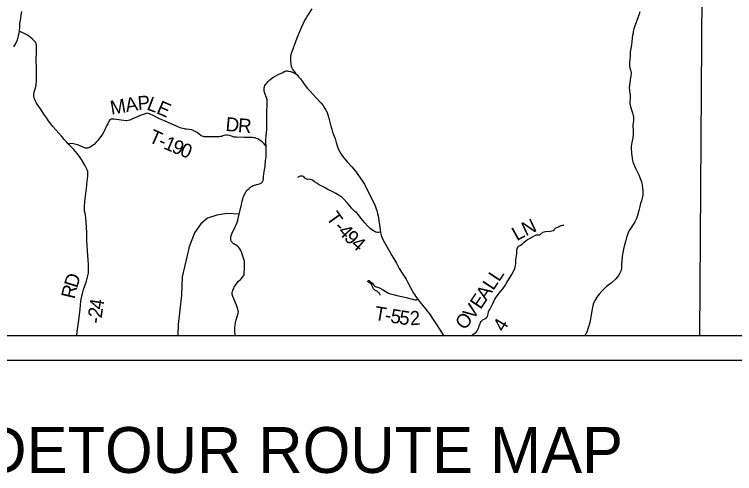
# Model space of a CAD drawing. Extents: x 0 to 191, y 0 to 55.
# Drawn here: x 22.6 to 26.995, y 8.927 to 11.729 of the extents above; entities that cross this region are included whole.
import ezdxf

# ---------------------------------------------------------------- set-up
doc = ezdxf.new("R2010")
doc.units = 0
for name, color, linetype in [('GM_X_County_Road', 7, 'Continuous'), ('GM_X_County_Road_Text', 7, 'Continuous'), ('GM_X_State_Route', 7, 'Continuous'), ('GM_X_Township_Road', 7, 'Continuous'), ('GM_X_Township_Road_Text', 7, 'Continuous'), ('GM_X_Township_Text', 7, 'Continuous'), ('SH_Data', 7, 'Continuous'), ('SH_Text', 7, 'Continuous')]:
    doc.layers.add(name, color=color, linetype=linetype)

msp = doc.modelspace()

# ---------------------------------------------------------------- linework, layer by layer
at = {"layer": 'GM_X_County_Road'}
for points in [[(24.4155, 11.7632), (24.389, 11.7228), (24.3798, 11.7084), (24.3732, 11.6965), (24.362, 11.6737), (24.3503, 11.6469), (24.3407, 11.6225), (24.3237, 11.5829), (24.3148, 11.5604), (24.2923, 11.5008), (24.289, 11.4913), (24.2866, 11.4819), (24.285, 11.4719), (24.2842, 11.4593), (24.2841, 11.4441), (24.2863, 11.427), (24.2895, 11.4129), (24.2938, 11.4026), (24.2999, 11.39), (24.3086, 11.3779), (24.3184, 11.366)], [(22.9807, 9.7697), (22.9831, 9.7942), (22.9867, 9.8209), (22.9935, 9.8627), (23.0015, 9.9305), (23.0062, 9.9785), (23.0092, 9.9993), (23.0148, 10.0251), (23.0225, 10.0508), (23.0397, 10.1012), (23.0483, 10.1332), (23.0519, 10.1522), (23.0527, 10.1756), (23.0522, 10.2014), (23.0504, 10.2331), (23.0477, 10.2553), (23.0421, 10.3484), (23.0409, 10.3987), (23.0365, 10.4894), (23.0346, 10.5022), (23.0314, 10.5161), (23.0286, 10.5278), (23.027, 10.5389), (23.0267, 10.5467), (23.0271, 10.5568), (23.0298, 10.5826), (23.0322, 10.6042), (23.037, 10.6522), (23.0409, 10.6857), (23.0418, 10.6928), (23.0443, 10.7095), (23.0476, 10.7425), (23.0484, 10.7575), (23.0473, 10.7697), (23.0458, 10.7757), (23.0442, 10.7804), (23.0383, 10.7934), (23.0296, 10.8089), (23.0084, 10.843), (22.9963, 10.8615), (22.9826, 10.8794), (22.9626, 10.9052), (22.9427, 10.9257), (22.9283, 10.9393), (22.9171, 10.9508), (22.9041, 10.9652), (22.8886, 10.9835), (22.852, 11.0237), (22.8348, 11.0443), (22.8217, 11.0612), (22.8084, 11.079), (22.7968, 11.0947), (22.7796, 11.1206), (22.7624, 11.1469), (22.7485, 11.1673), (22.7391, 11.1803), (22.7323, 11.1919), (22.7263, 11.2033), (22.7221, 11.2139), (22.7204, 11.2225), (22.719, 11.2306), (22.7186, 11.2406), (22.721, 11.2544), (22.7244, 11.2677), (22.7277, 11.2789), (22.7317, 11.2986), (22.7345, 11.3236), (22.7351, 11.3395), (22.7351, 11.3539), (22.7349, 11.376), (22.7343, 11.4064), (22.7332, 11.4474), (22.7346, 11.5038), (22.7354, 11.5236), (22.7346, 11.541), (22.7328, 11.5508), (22.729, 11.5584), (22.7228, 11.5659), (22.7086, 11.5797), (22.6947, 11.5914), (22.6797, 11.6021), (22.6601, 11.6123), (22.6427, 11.6201), (22.6301, 11.6241)], [(24.3184, 11.366), (24.3246, 11.3591), (24.3344, 11.3482), (24.3452, 11.335), (24.3742, 11.2951), (24.3877, 11.2776), (24.4021, 11.2618), (24.4394, 11.2213), (24.4702, 11.1893), (24.4835, 11.1733), (24.4946, 11.1556), (24.4999, 11.1451), (24.5077, 11.1295), (24.513, 11.1161), (24.5198, 11.0948), (24.5253, 11.0712), (24.5309, 11.0469), (24.5365, 11.0278), (24.5421, 11.0108), (24.5566, 10.9714), (24.5634, 10.9478), (24.5693, 10.9259), (24.5759, 10.9089), (24.585, 10.8911), (24.5942, 10.8752), (24.6024, 10.8638), (24.6312, 10.8294), (24.6586, 10.798), (24.6813, 10.7721), (24.6957, 10.7524), (24.711, 10.7307), (24.7291, 10.7041), (24.7363, 10.6919), (24.7451, 10.6753), (24.7573, 10.6512), (24.7645, 10.634), (24.7928, 10.5784), (24.8013, 10.5603), (24.8056, 10.5493), (24.8119, 10.5309), (24.8165, 10.5148), (24.82, 10.5004), (24.825, 10.4707), (24.8285, 10.4454), (24.8304, 10.4267), (24.8316, 10.4171), (24.8323, 10.4108), (24.8336, 10.3994), (24.8358, 10.3885), (24.8387, 10.3789), (24.8442, 10.365), (24.8509, 10.3512), (24.8586, 10.3372), (24.8668, 10.3225), (24.8916, 10.2794), (24.9043, 10.2573), (24.9196, 10.2317), (24.9316, 10.2111), (24.9404, 10.1943), (24.9482, 10.179), (24.9559, 10.1663), (24.963, 10.1553), (24.9785, 10.1317), (24.9901, 10.1135), (25.003, 10.0896), (25.0197, 10.0592), (25.0363, 10.0274), (25.0409, 10.0193), (25.0471, 10.0097), (25.0538, 10.0005), (25.0599, 9.9924), (25.0705, 9.9788), (25.0897, 9.9549), (25.1087, 9.9319), (25.123, 9.9149), (25.1323, 9.9025), (25.156, 9.8666), (25.1757, 9.8359), (25.1936, 9.8079), (25.2186, 9.7697)]]:
    msp.add_lwpolyline(points, dxfattribs=at)
at = {"layer": 'GM_X_State_Route'}
msp.add_lwpolyline([(22.5966, 11.5314), (22.6028, 11.5405), (22.6087, 11.5515), (22.6181, 11.574), (22.625, 11.597), (22.6301, 11.6241), (22.6312, 11.6313), (22.6323, 11.6514), (22.6336, 11.6745), (22.6384, 11.7042), (22.6416, 11.7243), (22.6459, 11.746)], dxfattribs=at)
at = {"layer": 'GM_X_Township_Road'}
for points in [[(26.4166, 11.7439), (26.4105, 11.7234), (26.4057, 11.7086), (26.4014, 11.6979), (26.3942, 11.6803), (26.3866, 11.6596), (26.381, 11.6412), (26.3769, 11.6241), (26.3752, 11.6142), (26.3728, 11.6011), (26.3702, 11.5837), (26.3652, 11.5427), (26.3616, 11.52), (26.3586, 11.4974), (26.357, 11.4765), (26.3553, 11.451), (26.3545, 11.4374), (26.3541, 11.4263), (26.3542, 11.4161), (26.3563, 11.4019), (26.3613, 11.3819), (26.3634, 11.3735), (26.3638, 11.3662), (26.3626, 11.3543), (26.3605, 11.3428), (26.3578, 11.3273), (26.3553, 11.3124), (26.3533, 11.2957), (26.3523, 11.2843), (26.3521, 11.2777), (26.3529, 11.2663), (26.3538, 11.2572), (26.3563, 11.2478), (26.3576, 11.2413), (26.3583, 11.2351), (26.3586, 11.2264), (26.3585, 11.218), (26.3563, 11.1929), (26.3567, 11.1836), (26.3577, 11.1771), (26.3595, 11.1684), (26.3624, 11.1581), (26.3666, 11.1455), (26.3723, 11.1275), (26.3747, 11.1196), (26.3761, 11.1126), (26.3777, 11.1013), (26.3781, 11.0883), (26.3777, 11.0782), (26.3762, 11.0701), (26.3744, 11.0547), (26.3747, 11.0414), (26.3758, 11.0294), (26.3766, 11.0122), (26.376, 10.998), (26.3736, 10.9755), (26.3678, 10.9475), (26.3652, 10.9344), (26.3639, 10.9219), (26.3646, 10.904), (26.3661, 10.8881), (26.3668, 10.8774), (26.3677, 10.8673), (26.3698, 10.8524), (26.3721, 10.8379), (26.3746, 10.8285), (26.3782, 10.8186), (26.3841, 10.8044), (26.3926, 10.7857), (26.4105, 10.7491), (26.4234, 10.7182), (26.4269, 10.7076), (26.4286, 10.6985), (26.4304, 10.6864), (26.436, 10.6523), (26.4346, 10.6277), (26.4318, 10.6085), (26.4269, 10.5905), (26.4212, 10.5741), (26.4168, 10.5556), (26.4106, 10.5321), (26.4023, 10.5009), (26.3962, 10.4826), (26.3932, 10.4745), (26.3871, 10.4632), (26.3753, 10.4461), (26.3616, 10.4252), (26.3525, 10.4096), (26.3459, 10.3958), (26.3353, 10.3669), (26.3292, 10.3437), (26.3222, 10.314), (26.3169, 10.2967), (26.3085, 10.2527), (26.3062, 10.2194), (26.3055, 10.2094), (26.3054, 10.1886), (26.3041, 10.1758), (26.303, 10.1702), (26.3009, 10.1626), (26.2949, 10.149), (26.2871, 10.1355), (26.2713, 10.1144), (26.2422, 10.0898), (26.2138, 10.0681), (26.2041, 10.0592), (26.1972, 10.052), (26.1854, 10.0395), (26.1692, 10.0214), (26.1608, 10.011), (26.1482, 9.9933), (26.1423, 9.9838), (26.1378, 9.9752), (26.1327, 9.9617), (26.1293, 9.9499), (26.1236, 9.9193), (26.1155, 9.8722), (26.111, 9.8493), (26.1017, 9.8169), (26.0955, 9.7966), (26.091, 9.7853), (26.087, 9.7785), (26.0821, 9.7716), (26.0797, 9.7697)], [(23.9468, 9.7697), (23.9459, 9.7998), (23.9459, 9.8192), (23.9475, 9.8304), (23.9496, 9.8458), (23.9539, 9.8641), (23.9613, 9.8922), (23.9654, 9.9052), (23.9666, 9.9129), (23.9661, 9.9202), (23.9633, 9.9303), (23.9599, 9.9414), (23.9555, 9.9537), (23.9386, 9.9929), (23.9333, 10.007), (23.9312, 10.0132), (23.9294, 10.0202), (23.9298, 10.0289), (23.9314, 10.0386), (23.9337, 10.0469), (23.9384, 10.0571), (23.9421, 10.0652), (23.9492, 10.077), (23.9588, 10.0899), (23.9685, 10.1005), (23.9814, 10.1125), (23.9947, 10.1279), (23.9982, 10.1327), (24.0011, 10.1406), (24.0028, 10.1517), (24.0037, 10.1811), (24.0038, 10.2086), (24.0032, 10.2222), (24.0005, 10.2351), (23.9966, 10.2483), (23.9908, 10.2652), (23.9867, 10.2778), (23.9824, 10.2888), (23.9758, 10.2989), (23.9692, 10.3069), (23.963, 10.3129), (23.9558, 10.3183), (23.9496, 10.322), (23.9434, 10.3262), (23.9356, 10.3312), (23.9312, 10.3345), (23.9285, 10.3383), (23.9237, 10.3446), (23.9215, 10.3529), (23.9205, 10.36), (23.9209, 10.3684), (23.9232, 10.3782), (23.9273, 10.3898), (23.9461, 10.428), (23.9518, 10.441), (23.9572, 10.455), (23.9629, 10.4739), (23.9712, 10.5105), (23.9851, 10.5688), (23.9902, 10.5886), (23.9966, 10.6119), (24.0045, 10.6306), (24.0094, 10.6401), (24.0144, 10.6482), (24.0184, 10.6533), (24.0244, 10.6594), (24.0334, 10.6674), (24.0437, 10.6763), (24.0506, 10.681), (24.0572, 10.6839), (24.0645, 10.6864), (24.087, 10.6925), (24.0954, 10.6954), (24.1052, 10.6987), (24.1108, 10.7024), (24.1146, 10.7073), (24.1179, 10.7154), (24.1195, 10.7255), (24.1203, 10.7391), (24.1224, 10.756), (24.1238, 10.7682), (24.1259, 10.7808), (24.1295, 10.801), (24.1308, 10.8095), (24.1329, 10.8348), (24.1357, 10.8588), (24.1373, 10.9077), (24.1362, 10.9255), (24.135, 10.9479), (24.1346, 10.9642), (24.1356, 10.9874), (24.1395, 11.0262), (24.1407, 11.046), (24.1414, 11.0793), (24.1406, 11.1154), (24.1411, 11.1438), (24.1416, 11.1642), (24.1424, 11.1828), (24.1432, 11.1943), (24.1427, 11.2016), (24.1418, 11.2096), (24.139, 11.2187), (24.1361, 11.2267), (24.1302, 11.2414), (24.1277, 11.2488), (24.1242, 11.2608), (24.1236, 11.2675), (24.1237, 11.2745), (24.1244, 11.2798), (24.1257, 11.2863), (24.129, 11.2942), (24.1327, 11.3004), (24.1378, 11.3079), (24.148, 11.3193), (24.1592, 11.3292), (24.1711, 11.3387), (24.1816, 11.3458), (24.1956, 11.3541), (24.2102, 11.3614), (24.2248, 11.3681), (24.2371, 11.3748), (24.2463, 11.3796), (24.2523, 11.3821), (24.2589, 11.3834), (24.2645, 11.3837), (24.2715, 11.3829), (24.2843, 11.3804), (24.2913, 11.3785), (24.2977, 11.3762), (24.3184, 11.366)], [(24.1362, 10.9255), (24.125, 10.9387), (24.1117, 10.9507), (24.1005, 10.9594), (24.0888, 10.9666), (24.078, 10.9716), (24.0688, 10.9746), (24.061, 10.9762), (24.0534, 10.9773), (24.043, 10.978), (24.0241, 10.9779), (24.0046, 10.9782), (23.9561, 10.9799), (23.9404, 10.9795), (23.9239, 10.9854), (23.9123, 10.99), (23.9002, 10.9923), (23.8937, 10.9927), (23.888, 10.992), (23.8795, 10.9901), (23.8719, 10.987), (23.8651, 10.9845), (23.8567, 10.9829), (23.8491, 10.9824), (23.8357, 10.9819), (23.8218, 10.982), (23.8031, 10.9811), (23.7892, 10.9808), (23.776, 10.9809), (23.7626, 10.981), (23.7575, 10.9817), (23.7533, 10.9829), (23.7444, 10.9866), (23.7375, 10.9903), (23.7276, 10.9984), (23.7175, 11.0057), (23.7103, 11.0105), (23.7032, 11.0143), (23.6979, 11.0172), (23.6927, 11.0194), (23.6799, 11.0237), (23.6671, 11.0263), (23.6504, 11.0282), (23.6437, 11.0288), (23.6384, 11.0296), (23.6275, 11.032), (23.6179, 11.0341), (23.6076, 11.0381), (23.5747, 11.0527), (23.5156, 11.079), (23.4859, 11.092), (23.4428, 11.1133), (23.4321, 11.1185), (23.4242, 11.122), (23.4159, 11.1243), (23.4091, 11.1255), (23.4028, 11.1238), (23.3971, 11.1215), (23.3862, 11.1175), (23.3684, 11.1109), (23.3613, 11.1079), (23.3357, 11.0972), (23.3118, 11.0869), (23.304, 11.0841), (23.2936, 11.0814), (23.2867, 11.0803), (23.281, 11.0802), (23.2648, 11.0818), (23.2506, 11.0835), (23.2087, 11.0905), (23.1985, 11.0904), (23.1899, 11.0889), (23.1835, 11.0862), (23.18, 11.0833), (23.1691, 11.0603), (23.1626, 11.0482), (23.1583, 11.0392), (23.1544, 11.0295), (23.1507, 11.0213), (23.1466, 11.0126), (23.1384, 10.9989), (23.1281, 10.9844), (23.1178, 10.9708), (23.1087, 10.9592), (23.0991, 10.9488), (23.088, 10.9376), (23.0733, 10.9256), (23.0617, 10.918), (23.0536, 10.9138), (23.0485, 10.9127), (23.0445, 10.9122), (23.0391, 10.9124), (23.0341, 10.9134), (23.0282, 10.9152), (23.0192, 10.9189), (23.0002, 10.9278), (22.9858, 10.9329), (22.9611, 10.9385), (22.9488, 10.9401), (22.9385, 10.9389), (22.9283, 10.9393)], [(24.8336, 10.3994), (24.8249, 10.398), (24.8165, 10.3986), (24.8062, 10.401), (24.7992, 10.404), (24.7932, 10.4069), (24.7792, 10.4158), (24.7705, 10.4233), (24.7628, 10.4308), (24.7542, 10.4396), (24.7381, 10.4574), (24.7165, 10.4843), (24.6996, 10.5067), (24.6868, 10.5194), (24.6784, 10.5264), (24.6729, 10.5308), (24.6664, 10.5367), (24.6626, 10.5406), (24.6566, 10.5473), (24.6463, 10.5597), (24.632, 10.5778), (24.6089, 10.6036), (24.5989, 10.6126), (24.5937, 10.6163), (24.5819, 10.6234), (24.5623, 10.6354), (24.5402, 10.6472), (24.5122, 10.661), (24.5022, 10.6657), (24.4916, 10.6716), (24.4712, 10.6826), (24.4557, 10.6915), (24.4447, 10.6986), (24.4319, 10.708), (24.4185, 10.7177), (24.4071, 10.7221), (24.3984, 10.7233), (24.3914, 10.722), (24.3845, 10.7227), (24.3789, 10.7247), (24.3755, 10.7273), (24.3725, 10.7303), (24.3682, 10.7347), (24.3623, 10.7392), (24.3584, 10.7413), (24.3543, 10.7423), (24.3494, 10.7425), (24.3447, 10.7411), (24.3279, 10.7329)], [(23.9712, 10.5105), (23.8965, 10.5129), (23.8354, 10.5035), (23.8115, 10.4956)], [(23.8115, 10.4956), (23.8025, 10.4926), (23.779, 10.4847), (23.7367, 10.4518), (23.6991, 10.3954), (23.6662, 10.3108), (23.6238, 10.1275), (23.6191, 10.0147), (23.6003, 9.8361), (23.5965, 9.7697)], [(25.5195, 9.9657), (25.5321, 9.9902), (25.5367, 9.9976), (25.5466, 10.0109), (25.5674, 10.0373), (25.581, 10.0543), (25.5943, 10.0744), (25.6056, 10.0935), (25.6312, 10.1353), (25.6397, 10.1504), (25.6477, 10.165), (25.6522, 10.1741), (25.6544, 10.1801), (25.6561, 10.1862), (25.6586, 10.1973), (25.6597, 10.2081), (25.6611, 10.23), (25.6657, 10.2706), (25.6667, 10.2915), (25.6675, 10.2979), (25.6694, 10.3042), (25.6735, 10.3106), (25.677, 10.3145), (25.6881, 10.3216), (25.698, 10.3269), (25.7018, 10.3306), (25.7109, 10.3396), (25.7321, 10.3544), (25.7478, 10.3642), (25.7653, 10.3738), (25.7799, 10.3811), (25.7865, 10.3834), (25.7923, 10.3845), (25.7991, 10.3834), (25.8061, 10.3829), (25.8249, 10.3993), (25.8326, 10.4021), (25.8404, 10.4034), (25.8701, 10.4056), (25.8892, 10.4099), (25.8948, 10.4131), (25.897, 10.4182), (25.9018, 10.4234), (25.9069, 10.4267), (25.916, 10.4299), (25.937, 10.4405), (25.9455, 10.4433), (25.9537, 10.4437)], [(24.8321, 10.0147), (24.8312, 10.0191), (24.829, 10.0235), (24.8258, 10.0289), (24.8224, 10.0325), (24.8163, 10.037), (24.8077, 10.0421), (24.8002, 10.047), (24.7953, 10.0505), (24.792, 10.0547), (24.7892, 10.0593), (24.785, 10.069), (24.7789, 10.0804), (24.7741, 10.0866), (24.7699, 10.0906), (24.7649, 10.0934), (24.7613, 10.0941), (24.7585, 10.0955), (24.7569, 10.0983), (24.7566, 10.1011), (24.7592, 10.1038), (24.7614, 10.1053), (24.7648, 10.1052), (24.7699, 10.1009), (24.7838, 10.0883), (24.7922, 10.0786), (24.7984, 10.0732), (24.8043, 10.069), (24.8092, 10.0666), (24.8143, 10.0645), (24.822, 10.0624), (24.8287, 10.06), (24.8467, 10.0496), (24.862, 10.0404), (24.8727, 10.0341), (24.8831, 10.0288), (24.8962, 10.0237), (24.9131, 10.0188), (24.9345, 10.0142), (24.9652, 10.0078), (24.9911, 10.0008), (25.0142, 9.9949), (25.0295, 9.9903), (25.036, 9.9886), (25.0432, 9.9865), (25.049, 9.9864), (25.0535, 9.988), (25.0599, 9.9924)], [(25.3905, 9.7697), (25.3976, 9.7746), (25.4181, 9.79), (25.4246, 9.7981), (25.4311, 9.8098), (25.4365, 9.8259), (25.4393, 9.8352), (25.4416, 9.8415), (25.4445, 9.8489), (25.4485, 9.8557), (25.455, 9.862), (25.461, 9.8669), (25.4703, 9.8718), (25.4795, 9.8773), (25.4835, 9.8812), (25.4876, 9.8864), (25.4902, 9.8936), (25.4916, 9.9023), (25.4937, 9.9144), (25.4955, 9.9196), (25.5006, 9.9291), (25.5195, 9.9657)]]:
    msp.add_lwpolyline(points, dxfattribs=at)
at = {"layer": 'GM_X_Township_Text'}
for points in [[(26.7829, 9.7697), (29.4489, 9.7697), (29.4489, 17.4562), (27.7742, 17.4846), (27.6359, 17.4861), (27.112, 17.4915), (26.9474, 17.4931), (26.8962, 17.4941)], [(20.0362, 17.3813), (20.0324, 17.1943), (20.0319, 17.1735), (20.0292, 17.0419), (20.0049, 15.5756), (20.0048, 15.5701), (19.9676, 13.3329), (19.8396, 13.3341), (19.2489, 13.3404), (19.2489, 9.7697), (26.7829, 9.7697)], [(26.7829, 9.7697), (26.7967, 11.8603), (26.8139, 13.1969), (26.8244, 13.6041), (26.8347, 14.7394), (26.8695, 15.9554), (26.8715, 16.1156), (26.8758, 16.3896), (26.8912, 16.8894), (26.8944, 17.0395), (26.8977, 17.0532), (26.8925, 17.2684), (26.8293, 17.269)]]:
    msp.add_lwpolyline(points, dxfattribs=at)
at = {"layer": 'SH_Data'}
for p, q in [((19.2489, 9.7697), (29.4489, 9.7697)), ((19.0989, 9.6197), (29.5989, 9.6197))]:
    msp.add_line(p, q, dxfattribs=at)

# ---------------------------------------------------------------- texts
at = {"layer": 'GM_X_County_Road_Text'}
for s, rotation, p in [('D', 72.9222, (22.9824, 10.0552)), ('R', 76.6321, (22.9666, 9.9885)), ('4', 81.0814, (23.1394, 9.924)), ('2', 82.3382, (23.1326, 9.8729)), ('-', 82.3931, (23.128, 9.8385))]:
    msp.add_text(s, height=0.0852, rotation=rotation, dxfattribs=at).set_placement(p)
at = {"layer": 'GM_X_Township_Road_Text'}
for s, rotation, p in [('M', 9.7678, (23.1921, 11.116)), ('A', 9.7073, (23.2832, 11.1317)), ('P', 4.7522, (23.3552, 11.1441)), ('L', 339.0422, (23.4026, 11.1502)), ('E', 336.3878, (23.4612, 11.1278)), ('D', 354.575, (23.8858, 11.0183)), ('R', 355.4077, (23.9618, 11.0111)), ('T', 335.9657, (23.4136, 10.9526)), ('-', 336.1185, (23.472, 10.9266)), ('1', 336.6202, (23.5048, 10.9121)), ('9', 337.4374, (23.5542, 10.8907)), ('0', 338.6826, (23.6045, 10.8698)), ('T', 305.6338, (24.4996, 10.4873)), ('N', 25.1883, (25.7204, 10.3743)), ('-', 314.0172, (24.5455, 10.4251)), ('4', 313.6016, (24.5697, 10.4)), ('L', 28.8157, (25.6658, 10.3442)), ('9', 314.6147, (24.607, 10.3608)), ('4', 318.7621, (24.6488, 10.3188)), ('L', 56.5615, (25.5575, 10.0932)), ('L', 56.2596, (25.5218, 10.0398)), ('E', 56.2393, (25.4447, 9.9244)), ('A', 56.2486, (25.4801, 9.9774)), ('T', 350.5419, (24.7933, 9.8656)), ('V', 54.1549, (25.3989, 9.8608)), ('-', 350.5551, (24.8562, 9.8551)), ('5', 350.6632, (24.8909, 9.8493)), ('5', 351.0876, (24.9434, 9.8407)), ('2', 3.9925, (25.0161, 9.8316)), ('O', 50.1389, (25.3468, 9.7981)), ('4', 59.1997, (25.5872, 9.7864))]:
    msp.add_text(s, height=0.0852, rotation=rotation, dxfattribs=at).set_placement(p)
at = {"layer": 'SH_Text'}
msp.add_text('DETOUR ROUTE MAP', height=0.28, dxfattribs=at).set_placement((22.4036, 8.9309))

doc.saveas('drawing.dxf')
